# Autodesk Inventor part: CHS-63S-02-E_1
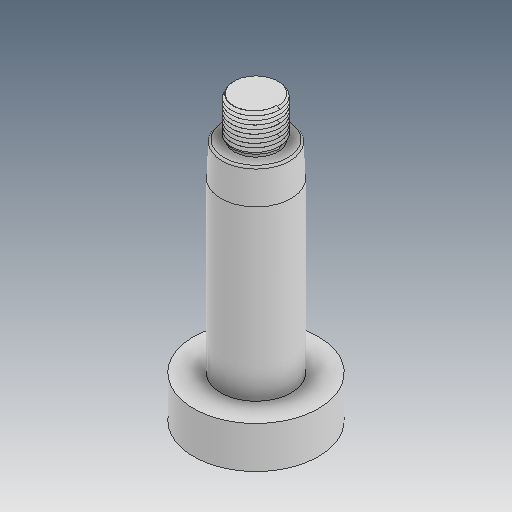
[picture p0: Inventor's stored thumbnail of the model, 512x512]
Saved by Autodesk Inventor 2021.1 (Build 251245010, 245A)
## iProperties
Created: 2019-05
Part Number: CHS-63S-02-E_1
Material: Ogólny
Document SubType Name: Modeling
Designer: user
Density: 1 g/cm^3
Appearance: Domyślna
Author: user
Revision Number: ÈÎºÎ
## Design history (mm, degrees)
feature "ÊäÈë1"
feature "ÊäÈë2"
node "Bryła1"
node "Bryła2"
